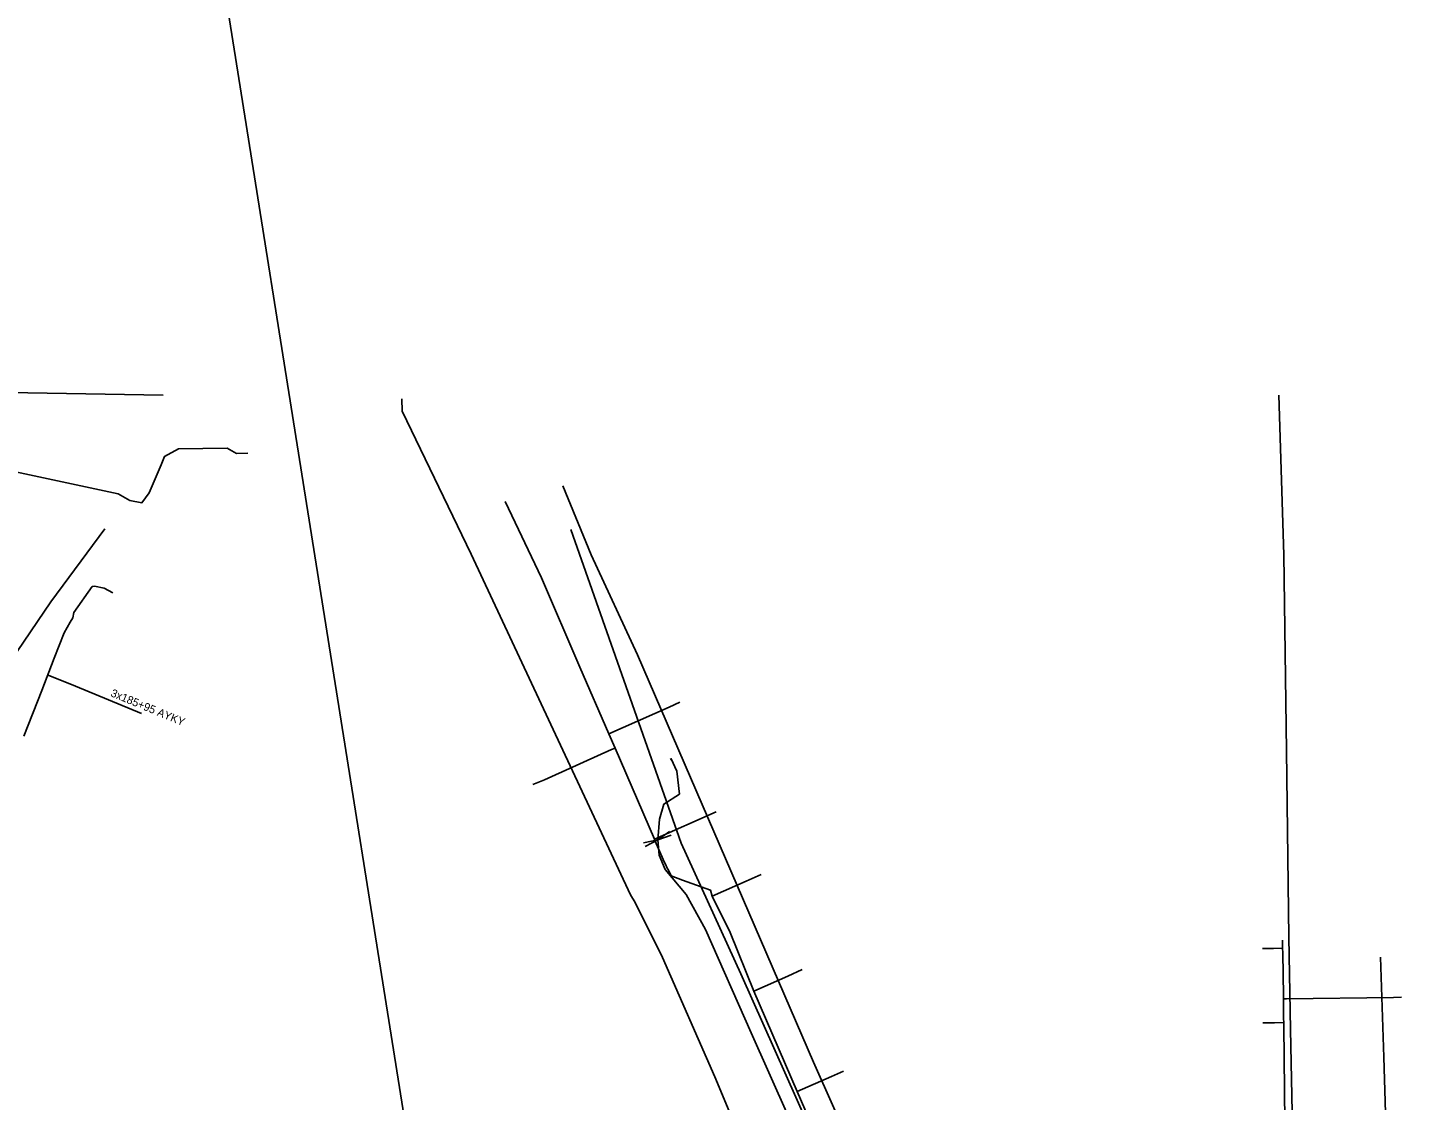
# Model space of a CAD drawing. Extents: x -748507 to -687366, y -1057342 to -1024924.
# Drawn here: x -736790.7 to -736619.1, y -1042318.2 to -1042184.2 of the extents above; entities that cross this region are included whole.
import ezdxf

# ---------------------------------------------------------------- set-up
doc = ezdxf.new("R2010")
doc.units = 0
for name, color, linetype in [('Kanalizace - pražské vodovody a kanalizace', 7, 'Continuous'), ('PRE - NN', 7, 'Continuous'), ('PRE - OK', 7, 'Continuous'), ('PRE - VN', 7, 'Continuous'), ('STL - PRAŽSKÁ PLYNÁRENSKÁ', 7, 'Continuous'), ('Telefonica O2', 7, 'Continuous'), ('UPC sdělovací kabel', 7, 'Continuous'), ('Vodovod - přežsko vodovody a kanalizace', 7, 'Continuous')]:
    doc.layers.add(name, color=color, linetype=linetype)

msp = doc.modelspace()

# ---------------------------------------------------------------- linework, layer by layer
at = {"layer": 'Kanalizace - pražské vodovody a kanalizace'}
msp.add_line((-736721.14, -1042461.73), (-736800.39, -1041964.08), dxfattribs=at)
for points in [[(-736693.65, -1042341.99), (-736698.06, -1042331.52), (-736704.86, -1042315.24), (-736711.38, -1042300.36), (-736714.81, -1042293.47), (-736715.38, -1042292.51), (-736735.3, -1042249.98), (-736743.94, -1042232.08), (-736743.98, -1042230.54)], [(-736634.41, -1042230.11), (-736633.78, -1042250.04), (-736633.45, -1042274.53), (-736633.15, -1042297.79), (-736632.93, -1042309.34), (-736632.42, -1042336.23), (-736683.29, -1042337.86), (-736693.34, -1042341.87)]]:
    msp.add_lwpolyline(points, dxfattribs=at)
at = {"layer": 'PRE - NN'}
for points in [[(-736791.18, -1042272.68), (-736788.93, -1042266.97), (-736787.4, -1042262.94), (-736786.16, -1042259.8), (-736785.4, -1042258.46), (-736785.07, -1042257.93), (-736784.94, -1042257.26), (-736782.63, -1042253.98), (-736782.37, -1042253.94), (-736781.15, -1042254.2), (-736780.05, -1042254.79)], [(-736788.13, -1042265.06), (-736784.73, -1042266.43), (-736776.48, -1042269.85)]]:
    msp.add_lwpolyline(points, dxfattribs=at)
at = {"layer": 'PRE - OK'}
msp.add_lwpolyline([(-736805.86, -1042236.77), (-736779.39, -1042242.42), (-736777.92, -1042243.24), (-736776.43, -1042243.54), (-736775.51, -1042242.32), (-736774.01, -1042238.81), (-736773.6, -1042237.76), (-736771.87, -1042236.82), (-736765.79, -1042236.73), (-736764.63, -1042237.38), (-736763.21, -1042237.35)], dxfattribs=at)
at = {"layer": 'PRE - VN'}
msp.add_lwpolyline([(-736684.73, -1042330.9), (-736692.54, -1042313.42), (-736714.53, -1042262.55), (-736720.32, -1042250.03), (-736723.84, -1042241.42)], dxfattribs=at)
at = {"layer": 'STL - PRAŽSKÁ PLYNÁRENSKÁ'}
for p, q in [((-736712.4, -1042285.57), (-736704.69, -1042282.15)), ((-736711.99, -1042285.66), (-736713.78, -1042286.03)), ((-736711.99, -1042285.66), (-736713.58, -1042286.49)), ((-736711.99, -1042285.66), (-736710.53, -1042284.59)), ((-736711.99, -1042285.66), (-736710.33, -1042285.05))]:
    msp.add_line(p, q, dxfattribs=at)
for points in [[(-736731.05, -1042243.38), (-736726.52, -1042252.9), (-736721.74, -1042264.07), (-736718.09, -1042272.42), (-736717.32, -1042274.19), (-736712.4, -1042285.56), (-736712.4, -1042285.57), (-736712.17, -1042286.11), (-736711.14, -1042288.49), (-736711, -1042288.76)], [(-736718.09, -1042272.42), (-736710.55, -1042269.07), (-736709.22, -1042268.45)], [(-736717.32, -1042274.19), (-736717.76, -1042274.38), (-736725.24, -1042277.74), (-736726.16, -1042278.15), (-736727.59, -1042278.72)], [(-736711.99, -1042285.66), (-736711.76, -1042283.07), (-736711.23, -1042281.18), (-736709.27, -1042279.93), (-736709.6, -1042277.08), (-736710.31, -1042275.51), (-736710.46, -1042275.59)], [(-736688.73, -1042335.59), (-736688.74, -1042335.29), (-736688.76, -1042334.99), (-736688.77, -1042334.69), (-736687.73, -1042334.68), (-736687.01, -1042334.48), (-736688.71, -1042333.04), (-736690.72, -1042330.33), (-736693.37, -1042325.35), (-736700.32, -1042309.75), (-736706.02, -1042296.86), (-736708.43, -1042292.48), (-736711.07, -1042289.35), (-736711.83, -1042287.55), (-736711.99, -1042285.66)], [(-736710.65, -1042289.45), (-736710.86, -1042289.11), (-736711, -1042288.76)], [(-736689.13, -1042332.58), (-736689.15, -1042332.5), (-736688.8, -1042331.77), (-736688.49, -1042331.27), (-736688.32, -1042330.82), (-736688.88, -1042329.39), (-736690.61, -1042326.21), (-736694.57, -1042317.07), (-736700, -1042304.55), (-736702.93, -1042297.2), (-736705.21, -1042292.66), (-736705.42, -1042291.91), (-736708.89, -1042290.67), (-736710.3, -1042290.13), (-736710.65, -1042289.45)], [(-736705.21, -1042292.66), (-736700.94, -1042290.82), (-736699.09, -1042289.96)], [(-736633.93, -1042299.19), (-736635.09, -1042299.21), (-736636.44, -1042299.21)], [(-736633.95, -1042298.19), (-736633.93, -1042299.19), (-736633.92, -1042299.74), (-736633.84, -1042305.11), (-736633.84, -1042305.51), (-736633.83, -1042305.91), (-736633.81, -1042307.98), (-736633.8, -1042308.48), (-736633.8, -1042308.88), (-736633.61, -1042324.95), (-736633.61, -1042325.45), (-736633.6, -1042325.85), (-736633.49, -1042334.25), (-736633.33, -1042336.41), (-736632.9, -1042342.39), (-736632.87, -1042342.89)], [(-736700, -1042304.55), (-736695.75, -1042302.68), (-736693.94, -1042301.82)], [(-736633.84, -1042305.51), (-736633.44, -1042305.51), (-736620.08, -1042305.32), (-736619.08, -1042305.31)], [(-736633.8, -1042308.48), (-736634.94, -1042308.49), (-736636.42, -1042308.5)], [(-736694.57, -1042317.07), (-736690.3, -1042315.22), (-736688.77, -1042314.52)]]:
    msp.add_lwpolyline(points, dxfattribs=at)
at = {"layer": 'Telefonica O2'}
for points in [[(-736773.77, -1042230.11), (-736814.92, -1042229.4), (-736820.16, -1042217.51), (-736840.16, -1042217.92), (-736984.6, -1042220.91), (-736984.42, -1042230.02), (-736984.97, -1042230.03)], [(-737002.21, -1042388.32), (-736983.88, -1042386.26), (-736958.25, -1042382.24), (-736935.04, -1042375.8), (-736916.74, -1042368.21), (-736899.05, -1042358.05), (-736887.23, -1042349.85), (-736886.54, -1042351.2), (-736879.64, -1042364.74), (-736874.64, -1042361.16), (-736868.56, -1042356.09), (-736852.88, -1042342.26), (-736841.94, -1042331.33), (-736838.86, -1042327.83), (-736832.26, -1042320.33), (-736825.16, -1042310.6), (-736818.96, -1042301.8), (-736787.8, -1042255.9), (-736781.08, -1042246.8)]]:
    msp.add_lwpolyline(points, dxfattribs=at)
at = {"layer": 'UPC sdělovací kabel'}
msp.add_lwpolyline([(-736621.69, -1042300.29), (-736621.31, -1042312.79), (-736621.08, -1042319.75)], dxfattribs=at)
at = {"layer": 'Vodovod - přežsko vodovody a kanalizace'}
msp.add_lwpolyline([(-736665.45, -1042477.56), (-736667.42, -1042461.42), (-736667.96, -1042451.99), (-736679.1, -1042351.8), (-736688.22, -1042334.91), (-736691.83, -1042324.31), (-736701.63, -1042302.37), (-736709.08, -1042286.06), (-736722.86, -1042246.88)], dxfattribs=at)

# ---------------------------------------------------------------- texts
at = {"layer": 'PRE - NN'}
msp.add_text('3x185+95 AYKY', height=1, rotation=337.5105, dxfattribs=at).set_placement((-736780.42, -1042267.68))

doc.saveas('drawing.dxf')
